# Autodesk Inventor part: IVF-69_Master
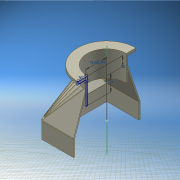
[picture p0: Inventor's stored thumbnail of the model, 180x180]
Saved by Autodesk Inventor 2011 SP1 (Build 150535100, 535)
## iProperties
Created: 2012-03
Part Number: IVF-69_Master
Material: Standard
Document SubType Name: Blech
Designer: Gawin
Density: 1 g/cm^3
Sheet Metal Rule: Standard_mm
Mass: 358.283 g
Surface Area: 1685.05 cm^2
Volume: 358.283 cm^3
Sheet Metal Width: 0,000 mm
Sheet Metal Length: 0,000 mm
Sheet Metal Area: 0,000 mm^2
Author: Gawin
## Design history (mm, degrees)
sketch "Skizze1"
  geometry: L1 (-100, 100)-(100, 100); L2 (100, 100)-(100, -100); L3 (100, -100)-(-100, -100); L4 (-100, -100)-(-100, 100); L5 (0, 100)-(0, -100); L6 (-100, 0)-(100, 0); 2 further points
  constraints: 12 end point, 6 midpoint, 2 parallel, 1 coincident, 1 horizontal, 1 perpendicular
  dimensions: "d2" = 200 distance of L1.start L1.end; "d3" = 200 distance of L3.end L1.start
sketch "Skizze2"
  geometry: L1 (0, 0)-(0, 120)
  constraints: 2 end point, 1 vertical
  dimensions: "d6" = 120 distance of L1.start L1.end
workplane "Arbeitsebene1"
sketch "Skizze3"
  geometry: C1 r 60 at (0, 0); C2 r 66 at (0, 0); C3 r 45 at (0, 0); 1 further point
  constraints: 3 centre point, 3 coincident
  dimensions: "d9" = 120 diameter of C1; "d16" = 6 radial gap between concentric circles of C2 C1; "d17" = 15 radial gap between concentric circles of C3 C1
node "Erhabene Lasche1"
extrude "Extrusion1" cut sketch "Skizze3" stored distance "d18" = 0; taper "d19" = 0 deg
sketch "Skizze4"
  geometry: L1 (-100, -99.664)-(-104, -99.664); L2 (-104, -99.664)-(-104, 99.664); L3 (-104, 99.664)-(-100, 99.664); L4 (-100, 99.664)-(-100, -99.664); L5 (-99.664, 100)-(99.664, 100); L6 (99.664, 100)-(99.664, 104); L7 (99.664, 104)-(-99.664, 104); L8 (-99.664, 104)-(-99.664, 100); L9 (100, 99.664)-(104, 99.664); L10 (104, 99.664)-(104, -99.664); L11 (104, -99.664)-(100, -99.664); L12 (100, -99.664)-(100, 99.664); L13 (99.664, -100)-(-99.664, -100); L14 (-99.664, -100)-(-99.664, -104); L15 (-99.664, -104)-(99.664, -104); L16 (99.664, -104)-(99.664, -100); 9 further points
  constraints: 32 end point, 8 parallel, 4 coincident, 4 horizontal, 4 perpendicular
  dimensions: "d20" = 4 distance of L10.end L11.end (= Stärke); "d21" = 4 distance of L15.end L13.start (= Stärke); "d22" = 4 distance of L1.start L1.end (= Stärke); "d23" = 4 distance of L7.end L5.start (= Stärke)
extrude "Extrusion2" join sketch "Skizze4" distance "d24" = 50; taper "d25" = 0 deg
feature "Biegung2" dims "d26" = 4 (= BreiteBiegungsfreistellung), "d27" = 2 (= TiefeBiegungsfreistellung), "d28" = 8 (= MinimalRest), "d29" = 4 (= Biegeradius), "d30" = 4 (= Biegeradius), "Stärke" = 4 (derived), "AbstandVerbindung" = 0.01
feature "Biegung3" dims "d31" = 4 (= BreiteBiegungsfreistellung), "d32" = 2 (= TiefeBiegungsfreistellung), "d33" = 8 (= MinimalRest), "d34" = 4 (= Biegeradius), "d35" = 4 (= Biegeradius), "Stärke" = 4 (derived), "AbstandVerbindung" = 0.01
feature "Biegung4" dims "d36" = 4 (= BreiteBiegungsfreistellung), "d37" = 2 (= TiefeBiegungsfreistellung), "d38" = 8 (= MinimalRest), "d39" = 4 (= Biegeradius), "d40" = 4 (= Biegeradius), "Stärke" = 4 (derived), "AbstandVerbindung" = 0.01
feature "Biegung5" dims "d41" = 4 (= BreiteBiegungsfreistellung), "d42" = 2 (= TiefeBiegungsfreistellung), "d43" = 8 (= MinimalRest), "d44" = 4 (= Biegeradius), "d45" = 4 (= Biegeradius), "Stärke" = 4 (derived), "AbstandVerbindung" = 0.01
sketch "Skizze7"
  geometry: L1 (-90.99, 142)-(-65.99, 142); L2 (-65.99, 142)-(-65.99, 70); L3 (-65.99, 70)-(-60.99, 70); L4 (-60.99, 70)-(-60.99, 150); L5 (-60.99, 150)-(-90.99, 150); L6 (-90.99, 150)-(-90.99, 142); L7 (0, -92)-(0, 202) reference; 2 further points
  constraints: 12 end point, 3 parallel, 2 perpendicular, 1 horizontal
  dimensions: "d59" = 8 distance of L5.end L1.start; "d60" = 5 distance between parallel lines of L4 L2; "d61" = 65.99 distance from line of point (0, 0) L2 (computed from d16, d9); "d62" = 30 distance from line of L5 point (0, 120); "d63" = 50 distance from line of point (0, 120) L3; "d65" = 30 distance of L4.end L5.end
revolve "Umdrehung1" stored, may be unused: angle "d64" = 90 deg
feature "Trennen1"
node "Volumenkörper1"
feature "Biegung1" dims "d11" = 4 (= Biegeradius), "d12" = 4 (= BreiteBiegungsfreistellung), "d13" = 2 (= TiefeBiegungsfreistellung), "d14" = 8 (= MinimalRest), "d15" = 4 (= Biegeradius), "Stärke" = 4 (derived), "AbstandVerbindung" = 0.01
other parameters: "KFaktor" = 4.4, "Biegeradius" = 4 (= Stärke), "BreiteBiegungsfreistellung" = 4 (= Stärke), "TiefeBiegungsfreistellung" = 2 (= 0.5 x Stärke), "GrößeEckenfreistellung" = 16 (= 4 x Stärke), "MinimalRest" = 8 (= 2 x Stärke), "Übergangsradius" = 4 (= Biegeradius), "JacobiRadiusGröße" = 4 (= Biegeradius), "Abstandsgröße" = 4 (= Stärke), "d10" = 15
